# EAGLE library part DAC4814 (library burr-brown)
Quad 12-Bit DAC Serial Interface
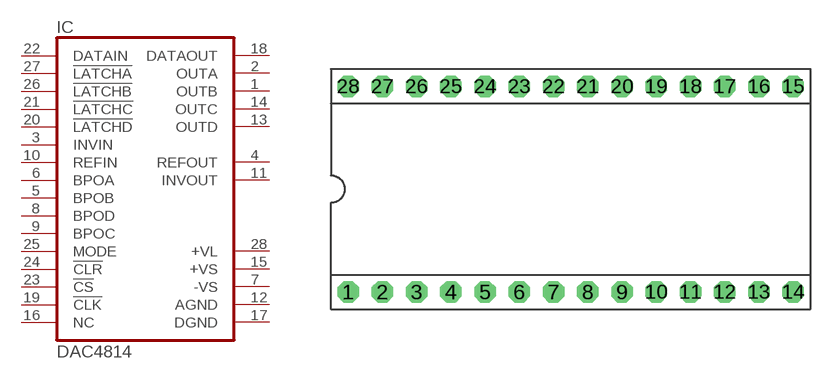
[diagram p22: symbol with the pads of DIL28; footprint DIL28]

Designator prefix IC

## DAC4814P (OC_FARNELL: unknown; OC_NEWARK: unknown)  [DIL28]
1  OUTB  out
2  OUTA  out
3  INVIN  in
4  REFOUT  out
5  BPOB  in
6  BPOA  in
7  -VS  pwr
8  BPOD  in
9  BPOC  in
10  REFIN  in
11  INVOUT  out
12  AGND  pwr
13  OUTD  out
14  OUTC  out
15  +VS  pwr
16  NC  nc
17  DGND  pwr
18  DATAOUT  out
19  !CLK  in
20  !LATCHD  in
21  !LATCHC  in
22  DATAIN  in
23  !CS  in
24  !CLR  in
25  MODE  in
26  !LATCHB  in
27  !LATCHA  in
28  +VL  pwr

## Footprint DIL28 (pad centres in mm)
Dual In Line
drill 0.813 pad 1.6 octagon: 1 -16.51,-7.62; 2 -13.97,-7.62; 3 -11.43,-7.62; 4 -8.89,-7.62; 5 -6.35,-7.62; 6 -3.81,-7.62; 7 -1.27,-7.62; 8 1.27,-7.62; 9 3.81,-7.62; 10 6.35,-7.62; 11 8.89,-7.62; 12 11.43,-7.62; 13 13.97,-7.62; 14 16.51,-7.62; 15 16.51,7.62; 16 13.97,7.62; 17 11.43,7.62; 18 8.89,7.62; 19 6.35,7.62; 20 3.81,7.62; 21 1.27,7.62; 22 -1.27,7.62; 23 -3.81,7.62; 24 -6.35,7.62; 25 -8.89,7.62; 26 -11.43,7.62; 27 -13.97,7.62; 28 -16.51,7.62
